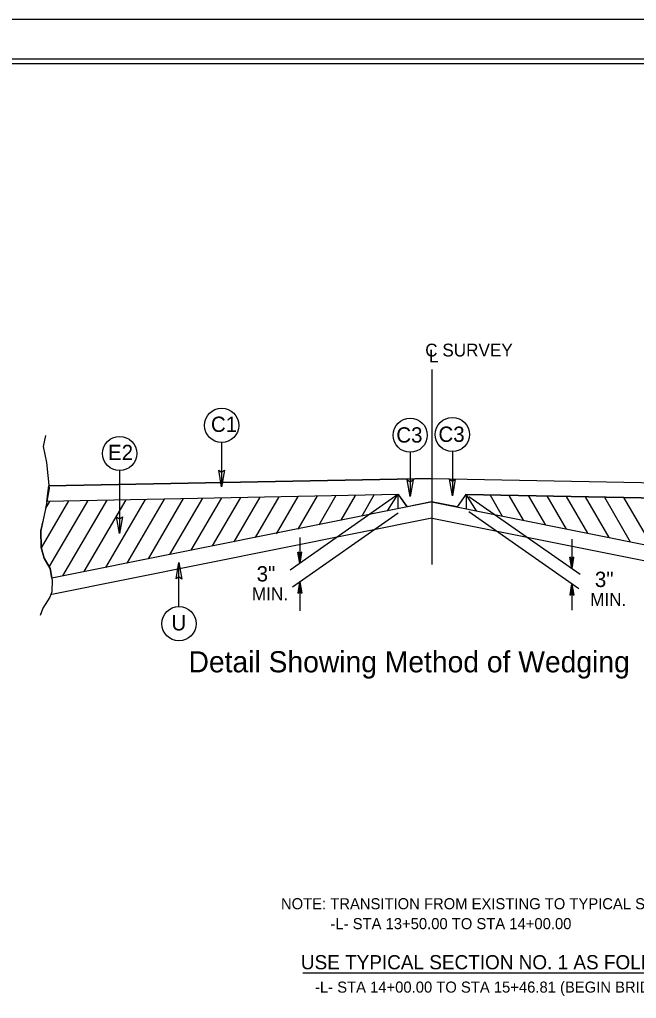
# Model space of a CAD drawing. Extents: x 55823 to 57507, y 47399 to 48499.
# Drawn here: x 56930 to 57278, y 47946 to 48499 of the extents above; entities that cross this region are included whole.
import ezdxf

# ---------------------------------------------------------------- set-up
doc = ezdxf.new("R2010")
doc.units = 0
for name, color, linetype in [('Old_Level_1', 7, 'Continuous'), ('Sheet Plot Border Inside CELL', 7, 'Continuous'), ('Sheet Plot Border Outside CELL', 7, 'Continuous'), ('Sheet Typical CELL', 7, 'Continuous'), ('Typical Detail Wedge2 CELL', 7, 'Continuous'), ('Typical ID Circle CELL', 7, 'Continuous'), ('Typical Terminator CELL', 7, 'Continuous'), ('Typical Text Centerline CELL', 7, 'Continuous'), ('Typical Text General CELL', 7, 'Continuous'), ('Typical Text ID Circle CELL', 7, 'Continuous')]:
    doc.layers.add(name, color=color, linetype=linetype)

msp = doc.modelspace()

# ---------------------------------------------------------------- linework, layer by layer
at = {"layer": 'Old_Level_1'}
msp.add_line((57090.02, 47960.92), (57330.68, 47960.92), dxfattribs=at)
at = {"layer": 'Sheet Plot Border Inside CELL'}
msp.add_lwpolyline([(57502.66, 48476.93), (55836.16, 48476.93), (55836.16, 47421.83), (57502.66, 47421.83)], close=True, dxfattribs=at)
at = {"layer": 'Sheet Plot Border Outside CELL'}
msp.add_lwpolyline([(57507.16, 48499.38), (55823.16, 48499.38), (55823.16, 47399.38), (57507.16, 47399.38)], close=True, dxfattribs=at)
at = {"layer": 'Sheet Typical CELL'}
msp.add_lwpolyline([(57490.16, 48474.38), (55990.16, 48474.38), (55990.16, 47424.38), (57490.16, 47424.38)], close=True, dxfattribs=at)
at = {"layer": 'Typical Detail Wedge2 CELL'}
for p, q in [((57162.98, 48191.49), (57162.98, 48301.78)), ((57162.98, 48191.49), (57162.98, 48266.81)), ((57162.97, 48240.21), (56946.53, 48235.89)), ((56946.53, 48235.89), (57162.97, 48240.21)), ((57162.97, 48240.21), (57379.43, 48235.89)), ((57162.99, 48240.21), (57379.43, 48235.89)), ((56945.3, 48227.19), (56946.53, 48235.89)), ((56957.62, 48227.44), (56942.22, 48201.04)), ((56946.82, 48227.22), (56944.6, 48223.42)), ((57143.98, 48231.16), (56945.3, 48227.19)), ((57143.98, 48231.16), (56945.3, 48227.19)), ((56968.42, 48227.66), (56946.93, 48190.83)), ((57163.3, 48226.91), (56948.15, 48183.87)), ((56979.22, 48227.87), (56954.25, 48185.09)), ((56990.02, 48228.09), (56966.34, 48187.51)), ((57000.82, 48228.3), (56978.42, 48189.92)), ((57011.62, 48228.52), (56990.51, 48192.34)), ((57022.42, 48228.74), (57002.59, 48194.76)), ((57033.22, 48228.95), (57014.68, 48197.18)), ((57044.02, 48229.17), (57026.76, 48199.59)), ((57054.82, 48229.38), (57038.85, 48202.01)), ((57065.62, 48229.6), (57050.93, 48204.43)), ((57076.42, 48229.81), (57063.02, 48206.85)), ((57087.22, 48230.03), (57074.92, 48208.95)), ((57143.74, 48231.01), (57082.75, 48188.29)), ((57098.02, 48230.25), (57087.13, 48211.56)), ((57108.71, 48230.46), (57098.94, 48213.71)), ((57119.48, 48230.43), (57111.38, 48216.56)), ((57130.35, 48230.99), (57123.29, 48218.89)), ((57137.83, 48221.91), (57143.71, 48231.09)), ((57143.71, 48231.09), (57143.71, 48223.54)), ((57148.85, 48224.04), (57143.98, 48231.16)), ((57143.98, 48230.93), (57148.85, 48224.04)), ((57162.65, 48226.91), (57148.85, 48224.04)), ((57162.65, 48226.91), (57377.8, 48183.87)), ((57177.1, 48224.04), (57162.65, 48226.91)), ((57182.12, 48231.16), (57177.1, 48224.04)), ((57182.12, 48231.16), (57177.1, 48224.04)), ((57181.8, 48231.01), (57182.11, 48230.99)), ((57182.12, 48231.16), (57380.67, 48227.19)), ((57380.67, 48227.19), (57182.12, 48231.16)), ((57188.12, 48221.91), (57182.25, 48231.09)), ((57182.25, 48231.09), (57182.25, 48222.78)), ((57183.78, 48230.01), (57246.61, 48186.01)), ((57195.6, 48230.99), (57202.67, 48218.89)), ((57206.46, 48230.43), (57214.56, 48216.56)), ((57217.24, 48230.46), (57227.02, 48213.71)), ((57227.93, 48230.25), (57238.82, 48211.56)), ((57238.74, 48230.03), (57250.86, 48209.26)), ((57249.54, 48229.82), (57262.93, 48206.85)), ((57260.34, 48229.6), (57275.01, 48204.43)), ((57271.13, 48229.38), (57287.09, 48202.01)), ((57143.88, 48220.57), (57084.2, 48178.78)), ((57183.69, 48221.46), (57245.91, 48177.9)), ((57162.89, 48217.65), (56948.08, 48174.68)), ((57163.06, 48217.65), (57378.37, 48174.57)), ((57088.31, 48206.7), (57088.31, 48192.19)), ((57242.01, 48205.86), (57242.01, 48189.23)), ((57088.31, 48192.19), (57087.19, 48198.55)), ((57088.31, 48197.72), (57087.19, 48198.55)), ((57088.31, 48192.19), (57087.35, 48198.43)), ((57087.5, 48198.31), (57088.31, 48192.19)), ((57088.31, 48192.19), (57089.44, 48198.55)), ((57089.44, 48198.55), (57088.31, 48197.72)), ((57089.28, 48198.43), (57088.31, 48192.19)), ((57088.31, 48192.19), (57089.1, 48198.31)), ((57088.31, 48192.19), (57087.66, 48198.2)), ((57087.83, 48198.08), (57088.31, 48192.19)), ((57088.31, 48192.19), (57087.99, 48197.96)), ((57088.15, 48197.84), (57088.31, 48192.19)), ((57088.94, 48198.2), (57088.31, 48192.19)), ((57088.31, 48192.19), (57088.79, 48198.08)), ((57088.63, 48197.96), (57088.31, 48192.19)), ((57088.31, 48192.19), (57088.47, 48197.84)), ((57088.31, 48197.72), (57088.31, 48192.19)), ((57242.01, 48189.23), (57240.89, 48195.6)), ((57242.01, 48194.77), (57240.89, 48195.6)), ((57242.01, 48189.23), (57241.05, 48195.48)), ((57241.21, 48195.36), (57242.01, 48189.23)), ((57242.01, 48189.23), (57241.37, 48195.24)), ((57241.53, 48195.12), (57242.01, 48189.23)), ((57242.01, 48189.23), (57241.69, 48195.01)), ((57241.85, 48194.89), (57242.01, 48189.23)), ((57242.01, 48189.23), (57243.14, 48195.6)), ((57243.14, 48195.6), (57242.01, 48194.77)), ((57242.97, 48195.48), (57242.01, 48189.23)), ((57242.01, 48189.23), (57242.81, 48195.36)), ((57242.65, 48195.24), (57242.01, 48189.23)), ((57242.01, 48189.23), (57242.49, 48195.12)), ((57242.33, 48195.01), (57242.01, 48189.23)), ((57242.01, 48189.23), (57242.17, 48194.89)), ((57242.01, 48194.77), (57242.01, 48189.23)), ((57088.31, 48181.66), (57087.19, 48175.29)), ((57087.35, 48175.42), (57088.31, 48181.66)), ((57088.31, 48181.66), (57087.5, 48175.53)), ((57087.66, 48175.66), (57088.31, 48181.66)), ((57088.31, 48181.66), (57087.83, 48175.77)), ((57087.99, 48175.88), (57088.31, 48181.66)), ((57088.31, 48181.66), (57088.15, 48176)), ((57088.31, 48181.66), (57088.31, 48165.32)), ((57088.31, 48181.66), (57089.44, 48175.29)), ((57088.31, 48176.12), (57088.31, 48181.66)), ((57088.47, 48176), (57088.31, 48181.66)), ((57088.31, 48181.66), (57088.63, 48175.88)), ((57088.79, 48175.77), (57088.31, 48181.66)), ((57088.31, 48181.66), (57088.94, 48175.66)), ((57089.1, 48175.53), (57088.31, 48181.66)), ((57088.31, 48181.66), (57089.28, 48175.42)), ((57242.01, 48180.62), (57240.89, 48174.26)), ((57241.05, 48174.38), (57242.01, 48180.62)), ((57242.01, 48180.62), (57241.21, 48174.49)), ((57241.37, 48174.62), (57242.01, 48180.62)), ((57242.01, 48180.62), (57241.53, 48174.73)), ((57241.69, 48174.84), (57242.01, 48180.62)), ((57242.01, 48180.62), (57241.85, 48174.96)), ((57242.01, 48180.62), (57242.01, 48165.74)), ((57242.01, 48180.62), (57243.14, 48174.26)), ((57242.01, 48175.08), (57242.01, 48180.62)), ((57242.17, 48174.96), (57242.01, 48180.62)), ((57242.01, 48180.62), (57242.33, 48174.84)), ((57242.49, 48174.73), (57242.01, 48180.62)), ((57242.01, 48180.62), (57242.65, 48174.62)), ((57242.81, 48174.49), (57242.01, 48180.62)), ((57242.01, 48180.62), (57242.97, 48174.38)), ((57087.19, 48175.29), (57088.31, 48176.12)), ((57088.31, 48176.12), (57089.44, 48175.29)), ((57240.89, 48174.26), (57242.01, 48175.08)), ((57242.01, 48175.08), (57243.14, 48174.26))]:
    msp.add_line(p, q, dxfattribs=at)
for points in [[(56944.52, 48264.46), (56943.36, 48258.12), (56945.1, 48249.1), (56946.63, 48234.51), (56944.52, 48222.98), (56942.03, 48210.51), (56942.22, 48201.09), (56943.75, 48195.15), (56947.21, 48189.19), (56948.36, 48182.67), (56948.17, 48176.14), (56947.01, 48173.06), (56942.99, 48166.92), (56941.64, 48162.69)], [(56948.14, 48183.87), (56947.21, 48189.19), (56943.75, 48195.15), (56942.22, 48201.09), (56942.03, 48210.51), (56943.18, 48216.29)]]:
    msp.add_lwpolyline(points, dxfattribs=at)
at = {"layer": 'Typical ID Circle CELL'}
for p, q in [((57044.11, 48260.47), (57044.11, 48235.49)), ((57150.66, 48254.92), (57150.66, 48229.93)), ((57174.48, 48255.31), (57174.48, 48230.33)), ((56986.47, 48244.59), (56986.47, 48209.06)), ((57019.99, 48167.78), (57019.99, 48192.76))]:
    msp.add_line(p, q, dxfattribs=at)
for centre in [(57044.11, 48270.14), (57150.66, 48264.58), (57174.48, 48264.98), (56986.46, 48254.25), (57019.99, 48158.11)]:
    msp.add_circle(centre, 9.67, dxfattribs=at)
at = {"layer": 'Typical Terminator CELL'}
for points in [[(57045.72, 48244.86), (57044.11, 48235.49), (57042.44, 48244.91), (57044.11, 48243.72)], [(57045.72, 48244.86), (57044.11, 48235.49), (57042.44, 48244.91), (57044.11, 48243.72)], [(57152.28, 48239.3), (57150.66, 48229.93), (57149, 48239.36), (57150.66, 48238.16)], [(57152.28, 48239.3), (57150.66, 48229.93), (57149, 48239.36), (57150.66, 48238.16)], [(57176.1, 48239.7), (57174.48, 48230.33), (57172.81, 48239.75), (57174.48, 48238.56)], [(57176.1, 48239.7), (57174.48, 48230.33), (57172.81, 48239.75), (57174.48, 48238.56)], [(56988.08, 48218.43), (56986.47, 48209.06), (56984.8, 48218.49), (56986.47, 48217.29)], [(56988.08, 48218.43), (56986.47, 48209.06), (56984.8, 48218.49), (56986.47, 48217.29)], [(57018.37, 48183.39), (57019.99, 48192.76), (57021.65, 48183.34), (57019.99, 48184.54)], [(57018.37, 48183.39), (57019.99, 48192.76), (57021.65, 48183.34), (57019.99, 48184.54)]]:
    msp.add_lwpolyline(points, close=True, dxfattribs=at)

# ---------------------------------------------------------------- texts
at = {"layer": 'Old_Level_1'}
for s, height, p in [('NOTE: TRANSITION FROM EXISTING TO TYPICAL SECTION NO. 1', 6.25, (57077.63, 47996.77)), ('-L- STA 13+50.00 TO STA 14+00.00', 6.25, (57105.62, 47985.52)), ('USE TYPICAL SECTION NO. 1 AS FOLLOWS', 8, (57088.9, 47962.85)), ('-L- STA 14+00.00 TO STA 15+46.81 (BEGIN BRIDGE)', 6.25, (57096.87, 47949.67))]:
    msp.add_text(s, height=height, dxfattribs=at).set_placement(p)
at = {"layer": 'Typical Detail Wedge2 CELL'}
for s, height, p in [('3"', 8.653, (57063.89, 48181.96)), ('3"', 8.653, (57255, 48178.82)), ('MIN.', 7.231, (57061.24, 48171.32)), ('MIN.', 7.231, (57252.34, 48168.18))]:
    msp.add_text(s, height=height, dxfattribs=at).set_placement(p)
at = {"layer": 'Typical Text Centerline CELL'}
for s, height, p in [('C SURVEY ', 7.231, (57159.15, 48309.06)), ('L', 7.23, (57161.27, 48305.67))]:
    msp.add_text(s, height=height, dxfattribs=at).set_placement(p)
at = {"layer": 'Typical Text General CELL'}
msp.add_text('Detail Showing Method of Wedging', height=11.9356, dxfattribs=at).set_placement((57025.41, 48130.61))
at = {"layer": 'Typical Text ID Circle CELL'}
for s, height, p in [('C1', 8.653, (57038.07, 48266.43)), ('C3', 8.653, (57142.8, 48260.41)), ('C3', 8.653, (57166.61, 48260.81)), ('E2', 8.653, (56979.92, 48250.5)), ('U', 8.65, (57015.76, 48154.28))]:
    msp.add_text(s, height=height, dxfattribs=at).set_placement(p)

doc.saveas('drawing.dxf')
